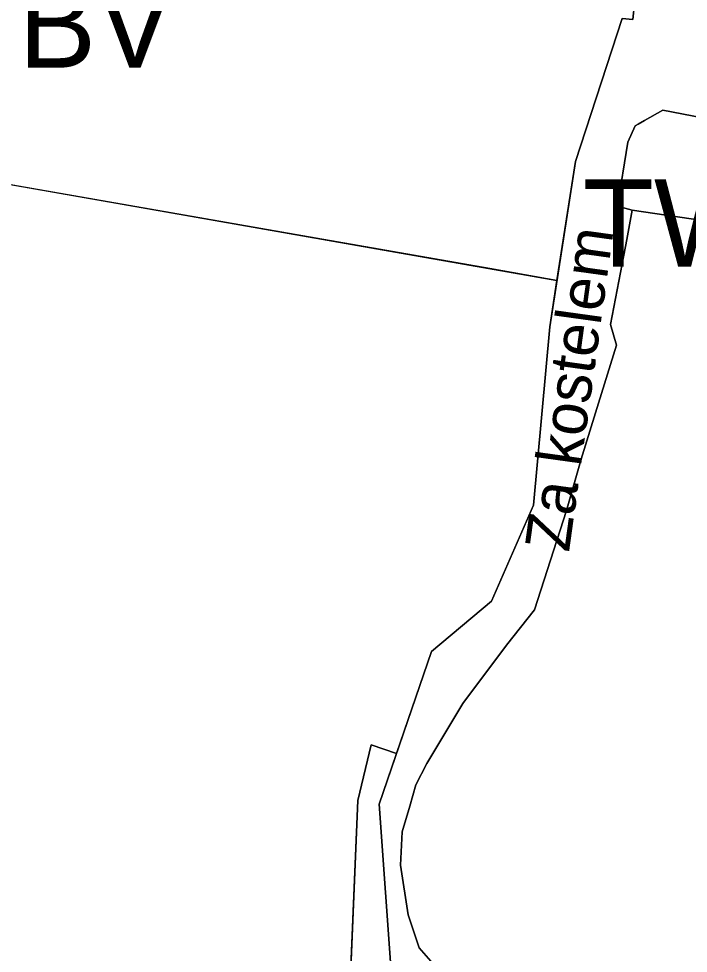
# Model space of a CAD drawing. Extents: x -555509 to -553005, y -1186756 to -1182560.
# Drawn here: x -554751 to -554643.5, y -1184692.3 to -1184542.3 of the extents above; entities that cross this region are included whole.
import ezdxf

# ---------------------------------------------------------------- set-up
doc = ezdxf.new("R2010")
doc.units = 0
for name, color, linetype in [('Level 15', 7, 'Continuous'), ('Level 36', 7, 'Continuous'), ('Level 52', 7, 'Continuous'), ('Level 57', 7, 'Continuous'), ('Level 59', 7, 'Continuous'), ('Level 6', 7, 'Continuous'), ('OBRYS_PLOCH', 7, 'Continuous'), ('stav_BV', 7, 'Continuous'), ('stav_PU', 7, 'Continuous'), ('stav_TW', 7, 'Continuous'), ('stav_ZZ', 7, 'Continuous')]:
    doc.layers.add(name, color=color, linetype=linetype)

msp = doc.modelspace()

# ---------------------------------------------------------------- linework, layer by layer
at = {"layer": 'Level 15'}
for points in [[(-554651.65, -1184534.63), (-554652.44, -1184542.42), (-554654.14, -1184542.26), (-554661.63, -1184565.18), (-554665.78, -1184591.72), (-554668.37, -1184620.38), (-554675.11, -1184635.77), (-554684.77, -1184643.87), (-554693.15, -1184668.37), (-554691.11, -1184696.73)], [(-554684.84, -1184693.59), (-554686.74, -1184691.45), (-554688.48, -1184686.14), (-554689.73, -1184678.16), (-554689.47, -1184672.84), (-554688.25, -1184668.72), (-554687.27, -1184665.29), (-554685.51, -1184661.85), (-554679.72, -1184652.21), (-554672.72, -1184642.88), (-554672.72, -1184642.88), (-554668.22, -1184637.2), (-554663.08, -1184621.21), (-554660.7, -1184613), (-554658.4, -1184605.57), (-554655.03, -1184594.67), (-554655.99, -1184591.35), (-554654.16, -1184581.63), (-554653.41, -1184577.71), (-554652.51, -1184573.02), (-554654.9, -1184572.37), (-554653.22, -1184562.07), (-554652.04, -1184559.48), (-554651.57, -1184559.21), (-554650.55, -1184558.64), (-554647.61, -1184556.97), (-554637.95, -1184558.83)], [(-554694.47, -1184658.87), (-554696.6, -1184667.81)], [(-554690.37, -1184660.23), (-554694.47, -1184658.87)], [(-554693.15, -1184668.37), (-554690.37, -1184660.23)], [(-554696.6, -1184667.81), (-554697.96, -1184701.13)], [(-554691.11, -1184696.73), (-554693.15, -1184668.37)]]:
    msp.add_lwpolyline(points, dxfattribs=at)
at = {"layer": 'Level 36'}
for points in [[(-554901.87, -1184553.35), (-554894.33, -1184553.82), (-554891.41, -1184554.08), (-554857.78, -1184552.7), (-554766.99, -1184566.47), (-554763.08, -1184567.16), (-554756.45, -1184568.21), (-554664.62, -1184584.28), (-554665.78, -1184591.72), (-554668.37, -1184620.38), (-554675.11, -1184635.77), (-554684.77, -1184643.87), (-554690.37, -1184660.23)], [(-554690.37, -1184660.23), (-554694.47, -1184658.87), (-554696.6, -1184667.81), (-554697.96, -1184701.13), (-554700.16, -1184781.85), (-554712.7, -1184848.47), (-554706.04, -1184849.97), (-554706.92, -1184853.88), (-554713.44, -1184852.4), (-554717.6, -1184874.5)]]:
    msp.add_lwpolyline(points, dxfattribs=at)
at = {"layer": 'Level 52'}
for points in [[(-554901.87, -1184553.35), (-554894.33, -1184553.82), (-554891.41, -1184554.08), (-554857.78, -1184552.7), (-554766.99, -1184566.47), (-554763.08, -1184567.16), (-554756.45, -1184568.21), (-554664.62, -1184584.28), (-554665.78, -1184591.72), (-554668.37, -1184620.38), (-554675.11, -1184635.77), (-554684.77, -1184643.87), (-554690.37, -1184660.23)], [(-554690.37, -1184660.23), (-554694.47, -1184658.87), (-554696.6, -1184667.81), (-554697.96, -1184701.13), (-554700.16, -1184781.85), (-554712.7, -1184848.47)]]:
    msp.add_lwpolyline(points, dxfattribs=at)
at = {"layer": 'Level 6'}
for points in [[(-554756.45, -1184568.21), (-554664.62, -1184584.28), (-554665.78, -1184591.72), (-554668.37, -1184620.38), (-554675.11, -1184635.77), (-554684.77, -1184643.87), (-554690.37, -1184660.23)], [(-554690.37, -1184660.23), (-554694.47, -1184658.87), (-554696.6, -1184667.81), (-554697.96, -1184701.13), (-554700.16, -1184781.85), (-554706.52, -1184815.63)]]:
    msp.add_lwpolyline(points, dxfattribs=at)
at = {"layer": 'OBRYS_PLOCH'}
for p, q in [((-554675.39, -1184582.4), (-554756.45, -1184568.21)), ((-554652.51, -1184573.02), (-554641.22, -1184574.69)), ((-554641.22, -1184574.69), (-554652.51, -1184573.02)), ((-554664.62, -1184584.28), (-554675.39, -1184582.4)), ((-554675.39, -1184582.4), (-554675.39, -1184582.4)), ((-554665.78, -1184591.72), (-554664.62, -1184584.28)), ((-554690.37, -1184660.23), (-554684.77, -1184643.87)), ((-554696.6, -1184667.81), (-554694.47, -1184658.87)), ((-554694.47, -1184658.87), (-554696.6, -1184667.81)), ((-554694.47, -1184658.87), (-554690.37, -1184660.23)), ((-554690.37, -1184660.23), (-554694.47, -1184658.87)), ((-554693.15, -1184668.37), (-554690.37, -1184660.23)), ((-554697.96, -1184701.13), (-554696.6, -1184667.81)), ((-554696.6, -1184667.81), (-554697.96, -1184701.13))]:
    msp.add_line(p, q, dxfattribs=at)
for points in [[(-554643.74, -1184513.22), (-554646.97, -1184520.1), (-554647.28, -1184523.42), (-554647.58, -1184523.38), (-554648.22, -1184527.77), (-554649.54, -1184527.64), (-554650.06, -1184533.35), (-554651.5, -1184533.21), (-554651.65, -1184534.63), (-554652.44, -1184542.42), (-554654.14, -1184542.26), (-554661.63, -1184565.18), (-554665.78, -1184591.72), (-554668.37, -1184620.38), (-554675.11, -1184635.77), (-554684.77, -1184643.87), (-554693.15, -1184668.37)], [(-554664.62, -1184584.28), (-554661.63, -1184565.18), (-554654.14, -1184542.26), (-554652.44, -1184542.42), (-554651.65, -1184534.63), (-554651.5, -1184533.21), (-554650.06, -1184533.35), (-554649.54, -1184527.64), (-554648.22, -1184527.77), (-554647.58, -1184523.38), (-554647.28, -1184523.42), (-554646.97, -1184520.1)], [(-554684.84, -1184693.59), (-554686.74, -1184691.45), (-554688.48, -1184686.14), (-554689.73, -1184678.16), (-554689.47, -1184672.84), (-554688.25, -1184668.72), (-554687.27, -1184665.29), (-554685.51, -1184661.85), (-554679.72, -1184652.21), (-554672.72, -1184642.88), (-554668.22, -1184637.2), (-554663.08, -1184621.21), (-554660.7, -1184613), (-554658.4, -1184605.57), (-554655.03, -1184594.67), (-554655.99, -1184591.35), (-554654.16, -1184581.63), (-554653.41, -1184577.71), (-554652.51, -1184573.02), (-554654.9, -1184572.37), (-554653.22, -1184562.07), (-554652.04, -1184559.48), (-554651.57, -1184559.21), (-554650.55, -1184558.64), (-554647.61, -1184556.97), (-554637.95, -1184558.83)], [(-554637.65, -1184559.89), (-554637.55, -1184558.91), (-554637.95, -1184558.83), (-554647.61, -1184556.97), (-554650.55, -1184558.64), (-554651.57, -1184559.21), (-554652.04, -1184559.48), (-554653.22, -1184562.07), (-554654.9, -1184572.37), (-554652.51, -1184573.02)], [(-554763.08, -1184567.16), (-554756.45, -1184568.21), (-554664.62, -1184584.28)], [(-554652.51, -1184573.02), (-554653.41, -1184577.71), (-554654.16, -1184581.63), (-554655.99, -1184591.35), (-554655.03, -1184594.67), (-554658.4, -1184605.57), (-554660.7, -1184613), (-554663.08, -1184621.21), (-554668.22, -1184637.2), (-554672.72, -1184642.88), (-554679.72, -1184652.21), (-554685.51, -1184661.85), (-554687.27, -1184665.29), (-554688.25, -1184668.72), (-554689.47, -1184672.84), (-554689.73, -1184678.16), (-554688.48, -1184686.14), (-554686.74, -1184691.45), (-554684.84, -1184693.59), (-554682.02, -1184695.35), (-554679.69, -1184695.78), (-554656.75, -1184695.11)], [(-554684.77, -1184643.87), (-554675.11, -1184635.77), (-554668.37, -1184620.38), (-554665.78, -1184591.72)]]:
    msp.add_lwpolyline(points, dxfattribs=at)
at = {"layer": 'stav_BV'}
msp.add_line((-554641.22, -1184574.69), (-554652.51, -1184573.02), dxfattribs=at)
for points in [[(-554664.62, -1184584.28), (-554661.63, -1184565.18), (-554654.14, -1184542.26), (-554652.44, -1184542.42), (-554651.65, -1184534.63), (-554651.5, -1184533.21), (-554650.06, -1184533.35), (-554649.54, -1184527.64), (-554648.22, -1184527.77), (-554647.58, -1184523.38), (-554647.28, -1184523.42), (-554646.97, -1184520.1)], [(-554763.08, -1184567.16), (-554756.45, -1184568.21), (-554664.62, -1184584.28)], [(-554652.51, -1184573.02), (-554653.41, -1184577.71), (-554654.16, -1184581.63), (-554655.99, -1184591.35), (-554655.03, -1184594.67), (-554658.4, -1184605.57), (-554660.7, -1184613), (-554663.08, -1184621.21), (-554668.22, -1184637.2), (-554672.72, -1184642.88), (-554679.72, -1184652.21), (-554685.51, -1184661.85), (-554687.27, -1184665.29), (-554688.25, -1184668.72), (-554689.47, -1184672.84), (-554689.73, -1184678.16), (-554688.48, -1184686.14), (-554686.74, -1184691.45), (-554684.84, -1184693.59), (-554682.02, -1184695.35), (-554679.69, -1184695.78), (-554656.75, -1184695.11)]]:
    msp.add_lwpolyline(points, dxfattribs=at)
at = {"layer": 'stav_PU'}
for p, q in [((-554694.47, -1184658.87), (-554696.6, -1184667.81)), ((-554690.37, -1184660.23), (-554694.47, -1184658.87)), ((-554693.15, -1184668.37), (-554690.37, -1184660.23)), ((-554696.6, -1184667.81), (-554697.96, -1184701.13))]:
    msp.add_line(p, q, dxfattribs=at)
for points in [[(-554643.74, -1184513.22), (-554646.97, -1184520.1), (-554647.28, -1184523.42), (-554647.58, -1184523.38), (-554648.22, -1184527.77), (-554649.54, -1184527.64), (-554650.06, -1184533.35), (-554651.5, -1184533.21), (-554651.65, -1184534.63), (-554652.44, -1184542.42), (-554654.14, -1184542.26), (-554661.63, -1184565.18), (-554665.78, -1184591.72), (-554668.37, -1184620.38), (-554675.11, -1184635.77), (-554684.77, -1184643.87), (-554693.15, -1184668.37)], [(-554684.84, -1184693.59), (-554686.74, -1184691.45), (-554688.48, -1184686.14), (-554689.73, -1184678.16), (-554689.47, -1184672.84), (-554688.25, -1184668.72), (-554687.27, -1184665.29), (-554685.51, -1184661.85), (-554679.72, -1184652.21), (-554672.72, -1184642.88), (-554668.22, -1184637.2), (-554663.08, -1184621.21), (-554660.7, -1184613), (-554658.4, -1184605.57), (-554655.03, -1184594.67), (-554655.99, -1184591.35), (-554654.16, -1184581.63), (-554653.41, -1184577.71), (-554652.51, -1184573.02), (-554654.9, -1184572.37), (-554653.22, -1184562.07), (-554652.04, -1184559.48), (-554651.57, -1184559.21), (-554650.55, -1184558.64), (-554647.61, -1184556.97), (-554637.95, -1184558.83)]]:
    msp.add_lwpolyline(points, dxfattribs=at)
at = {"layer": 'stav_TW'}
msp.add_line((-554652.51, -1184573.02), (-554641.22, -1184574.69), dxfattribs=at)
msp.add_lwpolyline([(-554637.65, -1184559.89), (-554637.55, -1184558.91), (-554637.95, -1184558.83), (-554647.61, -1184556.97), (-554650.55, -1184558.64), (-554651.57, -1184559.21), (-554652.04, -1184559.48), (-554653.22, -1184562.07), (-554654.9, -1184572.37), (-554652.51, -1184573.02)], dxfattribs=at)
at = {"layer": 'stav_ZZ'}
for p, q in [((-554675.39, -1184582.4), (-554756.45, -1184568.21)), ((-554664.62, -1184584.28), (-554675.39, -1184582.4)), ((-554675.39, -1184582.4), (-554675.39, -1184582.4)), ((-554665.78, -1184591.72), (-554664.62, -1184584.28)), ((-554690.37, -1184660.23), (-554684.77, -1184643.87)), ((-554696.6, -1184667.81), (-554694.47, -1184658.87)), ((-554694.47, -1184658.87), (-554690.37, -1184660.23)), ((-554697.96, -1184701.13), (-554696.6, -1184667.81))]:
    msp.add_line(p, q, dxfattribs=at)
msp.add_lwpolyline([(-554684.77, -1184643.87), (-554675.11, -1184635.77), (-554668.37, -1184620.38), (-554665.78, -1184591.72)], dxfattribs=at)

# ---------------------------------------------------------------- texts
at = {"layer": 'Level 57'}
msp.add_text('Za kostelem', height=7.1741, rotation=82.1031, dxfattribs=at).set_placement((-554662.69, -1184628.05))
at = {"layer": 'Level 59'}
for s, p in [('BV', (-554751.1, -1184550.13)), ('TW', (-554660.47, -1184582.07))]:
    msp.add_text(s, height=14, dxfattribs=at).set_placement(p)

doc.saveas('drawing.dxf')
